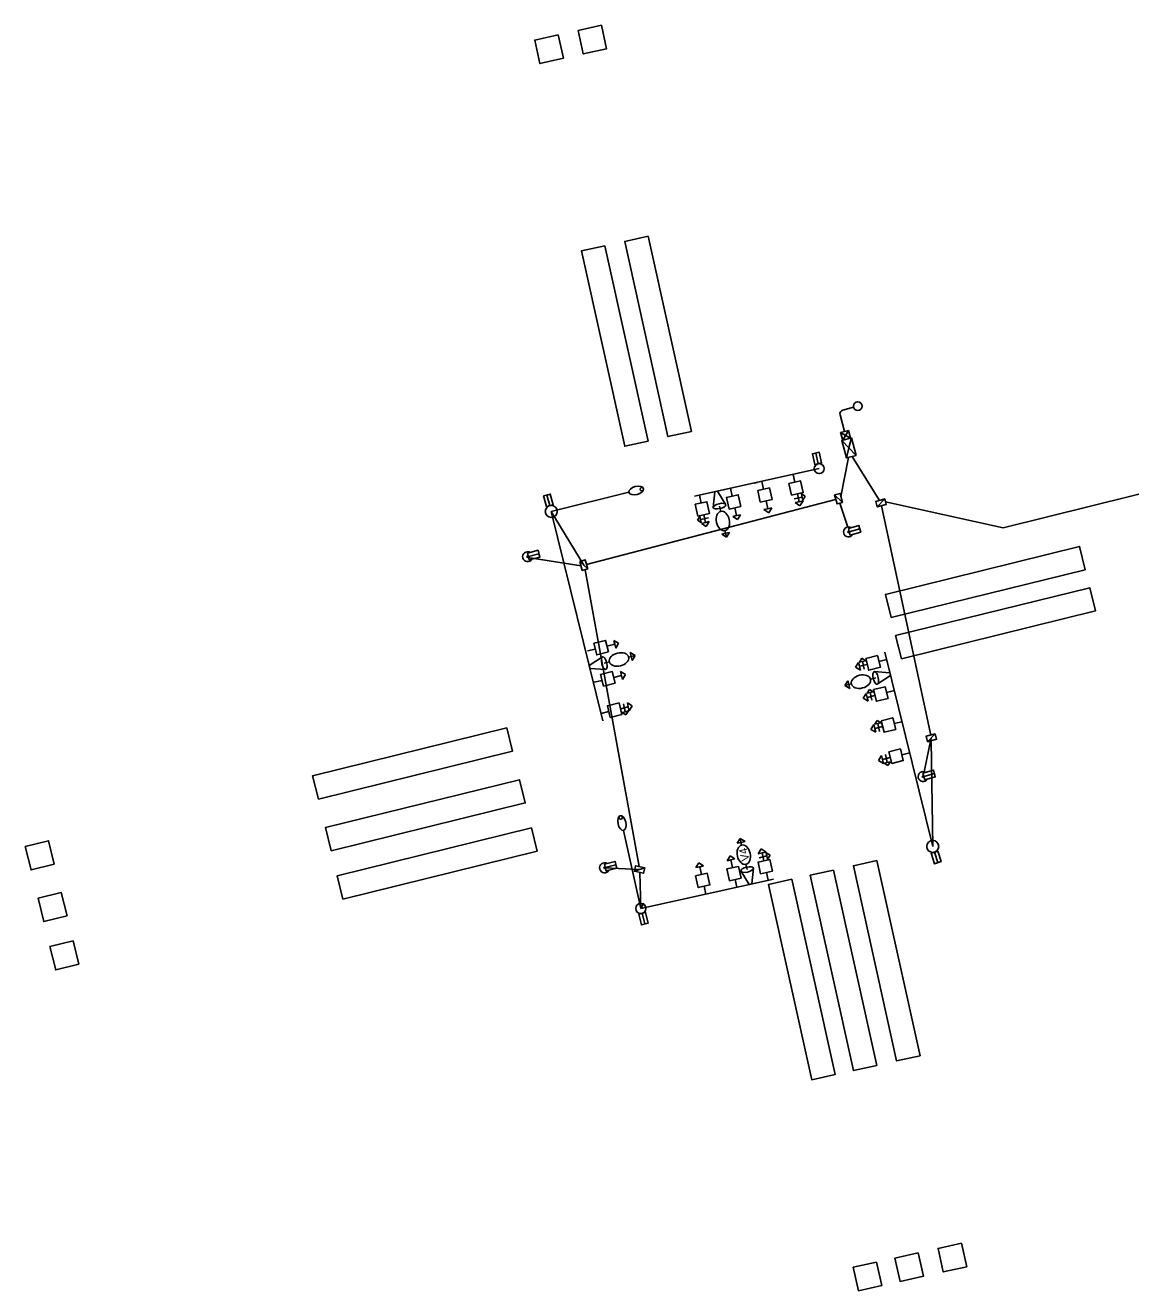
# Model space of a CAD drawing. Extents: x 647787 to 668496, y 640478 to 654412.
# Drawn here: x 666247.6 to 666524.1, y 641782.8 to 642099.1 of the extents above; entities that cross this region are included whole.
import ezdxf

# ---------------------------------------------------------------- set-up
doc = ezdxf.new("R2010")
doc.units = 0
for name, color, linetype in [('Default', 7, 'Continuous'), ('TEMP_DETECTION_ZONE_STAGE 5', 7, 'Continuous'), ('TEMP_SIGNAL_POLES_STAGE 5', 7, 'Continuous')]:
    doc.layers.add(name, color=color, linetype=linetype)

# ---------------------------------------------------------------- blocks, each defined once
blk = doc.blocks.new('pedhead')
at = {"layer": 'TEMP_DETECTION_ZONE_STAGE 5'}
for p, q in [((-2.75, 0.875), (0, 0.875)), ((-2.75, 0), (-2.75, 0.875)), ((-2.75, 0), (0, 0)), ((0, 0), (-2.75, 0)), ((0, 0.875), (0, 0))]:
    blk.add_line(p, q, dxfattribs=at)
for points in [[(0, -0.875), (0, 0.875), (-2.75, 0.875), (-2.75, -0.875)], [(-2.75, 0.875), (0, 0.875), (0, 0), (-2.75, 0)]]:
    blk.add_lwpolyline(points, close=True, dxfattribs=at)
blk = doc.blocks.new('signalcontroller')
at = {"layer": 'TEMP_DETECTION_ZONE_STAGE 5'}
for p, q in [((4.5, 1.25), (0, -1.25)), ((0, 1.25), (4.5, -1.25)), ((0, 1.25), (2.25, 0)), ((4.5, 1.25), (0, 1.25)), ((0, -1.25), (2.25, 0)), ((2.25, 0), (4.5, 1.25)), ((2.25, 0), (4.5, -1.25)), ((6.5, 1), (4.5, -1)), ((4.5, 1), (6.5, -1)), ((4.5, 1), (5.5, 0)), ((6.5, 1), (4.5, 1)), ((4.5, -1), (5.5, 0)), ((5.5, 0), (6.5, 1)), ((5.5, 0), (6.5, -1)), ((4.5, -1.25), (0, -1.25)), ((6.5, -1), (4.5, -1))]:
    blk.add_line(p, q, dxfattribs=at)
for points in [[(0, -1.25), (4.5, -1.25), (4.5, 1.25), (0, 1.25)], [(4.5, -1), (6.5, -1), (6.5, 1), (4.5, 1)]]:
    blk.add_lwpolyline(points, close=True, dxfattribs=at)
for points in [[(0, 1.25), (2.25, 0), (4.5, 1.25), (0, 1.25)], [(0, -1.25), (2.25, 0), (4.5, -1.25), (0, -1.25)], [(4.5, 1), (5.5, 0), (6.5, 1), (4.5, 1)], [(4.5, -1), (5.5, 0), (6.5, -1), (4.5, -1)]]:
    blk.add_lwpolyline(points, dxfattribs=at)
blk = doc.blocks.new('pullbox-type1')
at = {"layer": 'TEMP_DETECTION_ZONE_STAGE 5'}
for p, q in [((1.17, 0.71), (-1.17, -0.71)), ((1.17, -0.71), (1.17, 0.71)), ((-1.17, -0.71), (1.17, -0.71))]:
    blk.add_line(p, q, dxfattribs=at)
blk.add_lwpolyline([(1.17, -0.71), (1.17, 0.71), (-1.17, 0.71), (-1.17, -0.71)], close=True, dxfattribs=at)
blk.add_lwpolyline([(1.17, 0.71), (-1.17, -0.71), (1.17, -0.71), (1.17, 0.71)], dxfattribs=at)
blk = doc.blocks.new('videodetector')
at = {"layer": 'TEMP_DETECTION_ZONE_STAGE 5'}
for p, q in [((3.76, 0.05), (5.11, 0.05)), ((10.04, 0.05), (11.71, 0.05)), ((10.7, 0.05), (10.7, 1.05)), ((10.7, 1.05), (11.71, 0.05)), ((10.7, 0.05), (10.7, 1.05)), ((11.71, 0.05), (10.7, 1.05)), ((11.71, 0.05), (10.7, -0.96)), ((10.7, -0.96), (10.7, 0.05)), ((10.7, 0.05), (10.7, -0.96)), ((11.71, 0.05), (10.7, -0.96))]:
    blk.add_line(p, q, dxfattribs=at)
for points in [[(3.76, 1.68), (0, 0.37)], [(0, 0.37), (0, -0.37)], [(0, -0.37), (3.76, -1.58)]]:
    blk.add_lwpolyline(points, dxfattribs=at)
for centre, major_axis, ratio in [((3.76, 0.05), (0, 1.63), 0.386132), ((7.57, 0.05), (-2.47, 0), 0.662922)]:
    blk.add_ellipse(centre, major_axis=major_axis, ratio=ratio, dxfattribs=at)
blk.add_text('V4', height=2, dxfattribs=at).set_placement((5.93, -1.02))

msp = doc.modelspace()

# ---------------------------------------------------------------- linework, layer by layer
at = {"layer": 'Default'}
msp.add_lwpolyline([(666451.31, 641979.63), (666453.3, 641973.66)], dxfattribs=at)
at = {"layer": 'TEMP_DETECTION_ZONE_STAGE 5'}
for p, q in [((666440.05, 641984.85), (666439.62, 641986.8)), ((666440.05, 641984.85), (666439.62, 641986.8)), ((666424.43, 641981.39), (666424, 641983.34)), ((666424.43, 641981.39), (666424, 641983.34)), ((666432.24, 641983.12), (666431.81, 641985.07)), ((666432.25, 641983.1), (666431.81, 641985.06)), ((666432.25, 641983.1), (666431.81, 641985.06)), ((666416.62, 641979.66), (666416.19, 641981.61)), ((666433.33, 641978.22), (666432.9, 641980.17)), ((666441.9, 641981.16), (666439.94, 641980.73)), ((666441.14, 641979.97), (666440.15, 641979.75)), ((666440.15, 641979.75), (666441.14, 641979.97)), ((666441.35, 641978.99), (666440.15, 641979.75)), ((666441.35, 641978.99), (666440.15, 641979.75)), ((666441.14, 641979.97), (666440.7, 641981.92)), ((666441.14, 641979.97), (666442.12, 641980.19)), ((666441.14, 641979.97), (666442.12, 641980.19)), ((666441.35, 641978.99), (666442.12, 641980.19)), ((666442.12, 641980.19), (666441.35, 641978.99)), ((666441.9, 641981.16), (666441.72, 641981.95)), ((666442.68, 641981.34), (666441.72, 641981.95)), ((666441.9, 641981.16), (666441.72, 641981.95)), ((666441.72, 641981.95), (666442.68, 641981.34)), ((666441.9, 641981.16), (666442.07, 641980.38)), ((666442.07, 641980.38), (666441.9, 641981.16)), ((666442.68, 641981.34), (666442.07, 641980.38)), ((666442.68, 641981.34), (666442.07, 641980.38)), ((666415.73, 641975.37), (666416.34, 641976.32)), ((666415.73, 641975.37), (666416.34, 641976.32)), ((666416.51, 641975.54), (666416.34, 641976.32)), ((666416.34, 641976.32), (666416.51, 641975.54)), ((666417.7, 641974.78), (666417.27, 641976.73)), ((666421.25, 641978.88), (666421.54, 641977.57)), ((666425.51, 641976.51), (666424.53, 641976.29)), ((666424.53, 641976.29), (666425.51, 641976.51)), ((666425.73, 641975.53), (666424.53, 641976.29)), ((666425.73, 641975.53), (666424.53, 641976.29)), ((666425.51, 641976.51), (666425.08, 641978.46)), ((666425.51, 641976.51), (666426.49, 641976.73)), ((666425.51, 641976.51), (666426.49, 641976.73)), ((666425.73, 641975.53), (666426.49, 641976.73)), ((666426.49, 641976.73), (666425.73, 641975.53)), ((666433.33, 641978.22), (666432.35, 641978)), ((666432.35, 641978), (666433.33, 641978.22)), ((666433.55, 641977.24), (666432.35, 641978)), ((666433.55, 641977.24), (666432.35, 641978)), ((666433.33, 641978.22), (666434.31, 641978.44)), ((666433.33, 641978.22), (666434.31, 641978.44)), ((666433.55, 641977.24), (666434.31, 641978.44)), ((666434.31, 641978.44), (666433.55, 641977.24)), ((666415.73, 641975.37), (666416.68, 641974.75)), ((666416.68, 641974.75), (666415.73, 641975.37)), ((666416.51, 641975.54), (666418.46, 641975.97)), ((666416.51, 641975.54), (666416.68, 641974.75)), ((666416.51, 641975.54), (666416.68, 641974.75)), ((666417.7, 641974.78), (666416.72, 641974.56)), ((666416.72, 641974.56), (666417.7, 641974.78)), ((666417.92, 641973.8), (666416.72, 641974.56)), ((666417.92, 641973.8), (666416.72, 641974.56)), ((666417.7, 641974.78), (666418.68, 641975)), ((666417.7, 641974.78), (666418.68, 641975)), ((666417.92, 641973.8), (666418.68, 641975)), ((666418.68, 641975), (666417.92, 641973.8)), ((666422.75, 641972.1), (666421.77, 641971.89)), ((666421.77, 641971.89), (666422.75, 641972.1)), ((666422.96, 641971.12), (666421.77, 641971.89)), ((666422.96, 641971.12), (666421.77, 641971.89)), ((666422.6, 641972.75), (666422.96, 641971.12)), ((666422.75, 641972.1), (666423.73, 641972.32)), ((666422.75, 641972.1), (666423.73, 641972.32)), ((666422.96, 641971.12), (666423.73, 641972.32)), ((666423.73, 641972.32), (666422.96, 641971.12)), ((666395.02, 641944.35), (666394.78, 641945.33)), ((666395.99, 641944.59), (666394.78, 641945.33)), ((666395.02, 641944.35), (666394.78, 641945.33)), ((666394.78, 641945.33), (666395.99, 641944.59)), ((666395.99, 641944.59), (666395.26, 641943.38)), ((666395.99, 641944.59), (666395.26, 641943.38)), ((666390.16, 641943.15), (666388.22, 641942.68)), ((666395.02, 641944.35), (666393.08, 641943.87)), ((666395.02, 641944.35), (666395.26, 641943.38)), ((666395.26, 641943.38), (666395.02, 641944.35)), ((666398.48, 641941.14), (666400.1, 641941.54)), ((666399.12, 641941.3), (666398.88, 641942.28)), ((666400.1, 641941.54), (666398.88, 641942.28)), ((666399.12, 641941.3), (666398.88, 641942.28)), ((666398.88, 641942.28), (666400.1, 641941.54)), ((666400.1, 641941.54), (666399.36, 641940.33)), ((666400.1, 641941.54), (666399.36, 641940.33)), ((666392.39, 641939.64), (666393.69, 641939.96)), ((666399.12, 641941.3), (666399.36, 641940.33)), ((666399.36, 641940.33), (666399.12, 641941.3)), ((666455.27, 641938.61), (666456, 641939.82)), ((666455.27, 641938.61), (666456, 641939.82)), ((666455.27, 641938.61), (666456.48, 641937.87)), ((666456.48, 641937.87), (666455.27, 641938.61)), ((666456.24, 641938.85), (666456, 641939.82)), ((666456, 641939.82), (666456.24, 641938.85)), ((666456.83, 641940.85), (666456.21, 641939.89)), ((666456.21, 641939.89), (666456.83, 641940.85)), ((666457, 641940.06), (666456.21, 641939.89)), ((666457, 641940.06), (666456.21, 641939.89)), ((666456.24, 641938.85), (666458.19, 641939.33)), ((666456.24, 641938.85), (666456.48, 641937.87)), ((666456.24, 641938.85), (666456.48, 641937.87)), ((666456.83, 641940.85), (666457.78, 641940.24)), ((666456.83, 641940.85), (666457.78, 641940.24)), ((666457, 641940.06), (666457.78, 641940.24)), ((666457.78, 641940.24), (666457, 641940.06)), ((666457, 641940.06), (666457.43, 641938.11)), ((666461.1, 641940.04), (666463.04, 641940.52)), ((666391.86, 641935.33), (666389.92, 641934.85)), ((666396.72, 641936.53), (666394.78, 641936.05)), ((666396.72, 641936.53), (666396.48, 641937.51)), ((666397.69, 641936.77), (666396.48, 641937.51)), ((666396.72, 641936.53), (666396.48, 641937.51)), ((666396.48, 641937.51), (666397.69, 641936.77)), ((666396.72, 641936.53), (666396.96, 641935.55)), ((666396.96, 641935.55), (666396.72, 641936.53)), ((666397.69, 641936.77), (666396.96, 641935.55)), ((666397.69, 641936.77), (666396.96, 641935.55)), ((666452.59, 641934.02), (666453.32, 641935.24)), ((666452.59, 641934.02), (666453.32, 641935.24)), ((666453.56, 641934.26), (666453.32, 641935.24)), ((666453.32, 641935.24), (666453.56, 641934.26)), ((666460.3, 641935.92), (666458.99, 641935.6)), ((666454.2, 641934.42), (666452.59, 641934.02)), ((666452.59, 641934.02), (666453.8, 641933.29)), ((666453.8, 641933.29), (666452.59, 641934.02)), ((666453.56, 641934.26), (666453.8, 641933.29)), ((666453.56, 641934.26), (666453.8, 641933.29)), ((666457.18, 641930.84), (666457.92, 641932.06)), ((666457.18, 641930.84), (666457.92, 641932.06)), ((666458.16, 641931.08), (666457.92, 641932.06)), ((666457.92, 641932.06), (666458.16, 641931.08)), ((666458.74, 641933.08), (666458.13, 641932.12)), ((666458.13, 641932.12), (666458.74, 641933.08)), ((666458.91, 641932.3), (666458.13, 641932.12)), ((666458.91, 641932.3), (666458.13, 641932.12)), ((666458.74, 641933.08), (666459.7, 641932.47)), ((666458.74, 641933.08), (666459.7, 641932.47)), ((666458.91, 641932.3), (666459.7, 641932.47)), ((666459.7, 641932.47), (666458.91, 641932.3)), ((666458.91, 641932.3), (666459.35, 641930.34)), ((666463.01, 641932.28), (666464.96, 641932.76)), ((666463.01, 641932.28), (666464.96, 641932.76)), ((666398.42, 641928.71), (666396.47, 641928.23)), ((666397.66, 641927.49), (666397.23, 641929.45)), ((666398.42, 641928.71), (666398.18, 641929.69)), ((666399.39, 641928.95), (666398.18, 641929.69)), ((666398.42, 641928.71), (666398.18, 641929.69)), ((666398.18, 641929.69), (666399.39, 641928.95)), ((666398.42, 641928.71), (666398.66, 641927.73)), ((666398.66, 641927.73), (666398.42, 641928.71)), ((666399.39, 641928.95), (666398.66, 641927.73)), ((666399.39, 641928.95), (666398.66, 641927.73)), ((666457.18, 641930.84), (666458.4, 641930.11)), ((666458.4, 641930.11), (666457.18, 641930.84)), ((666458.16, 641931.08), (666460.1, 641931.56)), ((666458.16, 641931.08), (666458.4, 641930.11)), ((666458.16, 641931.08), (666458.4, 641930.11)), ((666393.56, 641927.51), (666391.62, 641927.03)), ((666397.66, 641927.49), (666396.88, 641927.32)), ((666396.88, 641927.32), (666397.66, 641927.49)), ((666397.84, 641926.71), (666396.88, 641927.32)), ((666397.84, 641926.71), (666396.88, 641927.32)), ((666397.66, 641927.49), (666398.45, 641927.67)), ((666397.66, 641927.49), (666398.45, 641927.67)), ((666397.84, 641926.71), (666398.45, 641927.67)), ((666398.45, 641927.67), (666397.84, 641926.71)), ((666459.1, 641923.07), (666459.83, 641924.29)), ((666459.1, 641923.07), (666459.83, 641924.29)), ((666459.1, 641923.07), (666460.32, 641922.34)), ((666460.32, 641922.34), (666459.1, 641923.07)), ((666460.07, 641923.31), (666459.83, 641924.29)), ((666459.83, 641924.29), (666460.07, 641923.31)), ((666460.66, 641925.31), (666460.04, 641924.36)), ((666460.04, 641924.36), (666460.66, 641925.31)), ((666460.83, 641924.53), (666460.04, 641924.36)), ((666460.83, 641924.53), (666460.04, 641924.36)), ((666460.07, 641923.31), (666462.02, 641923.79)), ((666460.07, 641923.31), (666460.32, 641922.34)), ((666460.07, 641923.31), (666460.32, 641922.34)), ((666460.66, 641925.31), (666461.61, 641924.7)), ((666460.66, 641925.31), (666461.61, 641924.7)), ((666460.83, 641924.53), (666461.61, 641924.7)), ((666461.61, 641924.7), (666460.83, 641924.53)), ((666460.83, 641924.53), (666461.26, 641922.58)), ((666464.93, 641924.51), (666466.87, 641924.99)), ((666464.93, 641924.51), (666466.87, 641924.99)), ((666461.01, 641915.31), (666461.75, 641916.52)), ((666461.01, 641915.31), (666461.75, 641916.52)), ((666461.99, 641915.55), (666461.75, 641916.52)), ((666461.75, 641916.52), (666461.99, 641915.55)), ((666461.99, 641915.55), (666463.93, 641916.02)), ((666463.18, 641914.81), (666462.74, 641916.76)), ((666466.84, 641916.74), (666468.79, 641917.22)), ((666466.84, 641916.74), (666468.79, 641917.22)), ((666461.01, 641915.31), (666462.23, 641914.57)), ((666462.23, 641914.57), (666461.01, 641915.31)), ((666461.99, 641915.55), (666462.23, 641914.57)), ((666461.99, 641915.55), (666462.23, 641914.57)), ((666463.18, 641914.81), (666462.39, 641914.64)), ((666462.39, 641914.64), (666463.18, 641914.81)), ((666463.35, 641914.02), (666462.39, 641914.64)), ((666463.35, 641914.02), (666462.39, 641914.64)), ((666463.18, 641914.81), (666463.96, 641914.98)), ((666463.18, 641914.81), (666463.96, 641914.98)), ((666463.35, 641914.02), (666463.96, 641914.98)), ((666463.96, 641914.98), (666463.35, 641914.02)), ((666423.87, 641891.44), (666423.11, 641890.24)), ((666423.11, 641890.24), (666423.87, 641891.44)), ((666423.87, 641891.44), (666425.07, 641890.68)), ((666423.87, 641891.44), (666425.07, 641890.68)), ((666431.68, 641893.17), (666430.92, 641891.97)), ((666430.92, 641891.97), (666431.68, 641893.17)), ((666431.9, 641892.19), (666430.92, 641891.97)), ((666431.9, 641892.19), (666430.92, 641891.97)), ((666433.09, 641891.43), (666431.14, 641891)), ((666431.68, 641893.17), (666432.88, 641892.41)), ((666431.68, 641893.17), (666432.88, 641892.41)), ((666431.9, 641892.19), (666432.88, 641892.41)), ((666432.88, 641892.41), (666431.9, 641892.19)), ((666431.9, 641892.19), (666432.33, 641890.24)), ((666433.09, 641891.43), (666432.92, 641892.21)), ((666433.88, 641891.6), (666432.92, 641892.21)), ((666433.09, 641891.43), (666432.92, 641892.21)), ((666432.92, 641892.21), (666433.88, 641891.6)), ((666433.09, 641891.43), (666433.27, 641890.64)), ((666433.27, 641890.64), (666433.09, 641891.43)), ((666433.88, 641891.6), (666433.27, 641890.64)), ((666433.88, 641891.6), (666433.27, 641890.64)), ((666416.06, 641889.71), (666415.3, 641888.51)), ((666415.3, 641888.51), (666416.06, 641889.71)), ((666416.28, 641888.73), (666415.3, 641888.51)), ((666416.28, 641888.73), (666415.3, 641888.51)), ((666416.06, 641889.71), (666417.26, 641888.95)), ((666416.06, 641889.71), (666417.26, 641888.95)), ((666416.28, 641888.73), (666417.26, 641888.95)), ((666417.26, 641888.95), (666416.28, 641888.73)), ((666416.28, 641888.73), (666416.71, 641886.78)), ((666424.09, 641890.46), (666423.11, 641890.24)), ((666424.09, 641890.46), (666423.11, 641890.24)), ((666424.09, 641890.46), (666425.07, 641890.68)), ((666425.07, 641890.68), (666424.09, 641890.46)), ((666424.09, 641890.46), (666424.52, 641888.51)), ((666425.17, 641885.58), (666425.6, 641883.62)), ((666432.98, 641887.31), (666433.41, 641885.35)), ((666417.36, 641883.85), (666417.79, 641881.89)), ((666402.31, 641879.6), (666401.56, 641878.3))]:
    msp.add_line(p, q, dxfattribs=at)
for points in [[(666462.75, 641979.99), (666492.21, 641973.49), (666665.6, 642016.47), (666782.14, 642043.1), (666870.44, 642058.1), (666911.78, 642069.17)], [(666451.38, 642001.67), (666452.49, 641997.53)], [(666454.75, 642003.61), (666452.09, 642002.89)], [(666453.49, 641991.07), (666451.59, 641981.29)], [(666454.41, 641991.31), (666461.23, 641980.32)], [(666446.18, 641988.26), (666414.94, 641981.34)], [(666420.02, 641982.46), (666419.66, 641978.53)], [(666422.84, 641979.23), (666420.75, 641982.62)], [(666422.93, 641983.11), (666422.2, 641982.95)], [(666430.75, 641984.82), (666430.02, 641984.66)], [(666379.16, 641977.55), (666398.58, 641982.34)], [(666450.2, 641980.53), (666387.97, 641964.3)], [(666379.16, 641977.55), (666392.06, 641925.24)], [(666387.29, 641964.12), (666379.16, 641977.55)], [(666461.77, 641978.99), (666474.05, 641921.66)], [(666386.6, 641963.93), (666373.29, 641966.06)], [(666387.59, 641962.99), (666401.11, 641888.8)], [(666474.56, 641893.81), (666462.59, 641942.36)], [(666392, 641941.22), (666388.66, 641939.06)], [(666388.66, 641939.06), (666388.83, 641938.33)], [(666388.83, 641938.33), (666392.78, 641938.06)], [(666463.85, 641937.23), (666459.91, 641937.5)], [(666460.69, 641934.34), (666464.03, 641936.51)], [(666464.03, 641936.51), (666463.85, 641937.23)], [(666474.2, 641920.97), (666472.4, 641912.5)], [(666474.16, 641920.22), (666474.56, 641893.81)], [(666401.56, 641878.3), (666397.23, 641897.82)], [(666401.25, 641888.04), (666392.49, 641888.47)], [(666401.27, 641887.31), (666401.56, 641878.3)], [(666401.56, 641878.3), (666434.75, 641885.65)]]:
    msp.add_lwpolyline(points, dxfattribs=at)
for points in [[(666431.43, 641979.85), (666434.36, 641980.5), (666433.71, 641983.43), (666430.78, 641982.78)], [(666439.24, 641981.6), (666442.17, 641982.25), (666441.52, 641985.18), (666438.59, 641984.53)], [(666415.81, 641976.41), (666418.74, 641977.06), (666418.09, 641979.99), (666415.16, 641979.34)], [(666423.62, 641978.14), (666426.55, 641978.79), (666425.9, 641981.72), (666422.97, 641981.07)], [(666393.44, 641942.42), (666392.72, 641945.33), (666389.8, 641944.61), (666390.52, 641941.7)], [(666457.83, 641940.78), (666458.55, 641937.87), (666461.46, 641938.59), (666460.74, 641941.5)], [(666395.13, 641934.6), (666394.42, 641937.51), (666391.5, 641936.79), (666392.22, 641933.88)], [(666459.74, 641933.02), (666460.46, 641930.1), (666463.37, 641930.82), (666462.66, 641933.73)], [(666396.83, 641926.77), (666396.12, 641929.69), (666393.2, 641928.97), (666393.92, 641926.06)], [(666461.66, 641925.25), (666462.38, 641922.34), (666465.29, 641923.05), (666464.57, 641925.97)], [(666463.57, 641917.48), (666464.29, 641914.57), (666467.2, 641915.29), (666466.49, 641918.2)], [(666425.99, 641888.83), (666423.06, 641888.18), (666423.71, 641885.25), (666426.63, 641885.9)], [(666433.8, 641890.56), (666430.87, 641889.91), (666431.52, 641886.98), (666434.45, 641887.63)], [(666418.18, 641887.1), (666415.25, 641886.45), (666415.9, 641883.52), (666418.82, 641884.17)]]:
    msp.add_lwpolyline(points, close=True, dxfattribs=at)
for centre, radius in [((666455.79, 642003.89), 1.08), ((666446.18, 641988.26), 1.25), ((666446.18, 641988.26), 1.25), ((666401.8, 641983.13), 0.441), ((666379.16, 641977.55), 1.5), ((666379.16, 641977.55), 1.5), ((666453.5, 641972.43), 0.188), ((666453.5, 641972.43), 0.187), ((666373.24, 641966.24), 0.188), ((666373.24, 641966.24), 0.187), ((666472.14, 641911.28), 0.188), ((666472.14, 641911.28), 0.187), ((666396.52, 641901.05), 0.441), ((666474.56, 641893.81), 1.5), ((666474.56, 641893.81), 1.5), ((666392.49, 641888.47), 0.188), ((666392.49, 641888.47), 0.187), ((666401.56, 641878.3), 1.25), ((666401.56, 641878.3), 1.25)]:
    msp.add_circle(centre, radius, dxfattribs=at)
for centre, radius, start, end in [((666452.35, 642001.93), 1, 105, 195), ((666453.5, 641972.43), 1.25, 59.427, 330.573), ((666373.24, 641966.24), 1.25, 59.427, 330.573), ((666472.14, 641911.28), 1.25, 59.427, 330.573), ((666392.49, 641888.47), 1.25, 59.427, 330.573)]:
    msp.add_arc(centre, radius, start, end, dxfattribs=at)
for centre, major_axis, ratio in [((666400.4, 641982.79), (1.82, 0.45), 0.533333), ((666421.25, 641978.88), (1.59, 0.35), 0.386132), ((666422.07, 641975.16), (-0.53, 2.41), 0.662922), ((666396.09, 641940.55), (-2.4, -0.59), 0.662922), ((666392.39, 641939.64), (-0.39, 1.58), 0.386132), ((666456.6, 641935.01), (2.4, 0.59), 0.662922), ((666460.3, 641935.92), (0.39, -1.58), 0.386132), ((666396.83, 641899.66), (-0.41, 1.83), 0.533333)]:
    msp.add_ellipse(centre, major_axis=major_axis, ratio=ratio, dxfattribs=at)
at = {"layer": 'TEMP_SIGNAL_POLES_STAGE 5'}
for points in [[(666380.89, 642096.69), (666375.03, 642095.39), (666376.33, 642089.53), (666382.18, 642090.83)], [(666391.71, 642099.08), (666385.85, 642097.78), (666387.15, 642091.93), (666393, 642093.22)], [(666403.38, 642046.36), (666397.53, 642045.06), (666408.34, 641996.25), (666414.2, 641997.54)], [(666392.56, 642043.96), (666386.71, 642042.67), (666397.52, 641993.85), (666403.38, 641995.15)], [(666464.17, 641951.01), (666512.72, 641962.98), (666511.28, 641968.8), (666462.74, 641956.83)], [(666466.71, 641940.7), (666515.26, 641952.67), (666513.82, 641958.49), (666465.28, 641946.52)], [(666320.9, 641905.66), (666319.46, 641911.49), (666368.01, 641923.45), (666369.45, 641917.62)], [(666324.09, 641892.71), (666322.65, 641898.54), (666371.2, 641910.5), (666372.64, 641904.67)], [(666327.06, 641880.65), (666325.62, 641886.48), (666374.17, 641898.45), (666375.61, 641892.62)], [(666254.87, 641889.39), (666253.44, 641895.22), (666247.61, 641893.78), (666249.05, 641887.95)], [(666449.75, 641887.89), (666443.89, 641886.6), (666454.7, 641837.78), (666460.56, 641839.08)], [(666460.57, 641890.29), (666454.71, 641888.99), (666465.53, 641840.18), (666471.38, 641841.47)], [(666439.34, 641885.59), (666433.48, 641884.29), (666444.29, 641835.47), (666450.15, 641836.77)], [(666258.06, 641876.46), (666256.62, 641882.29), (666250.8, 641880.85), (666252.23, 641875.02)], [(666261.04, 641864.37), (666259.6, 641870.2), (666253.78, 641868.76), (666255.21, 641862.93)], [(666481.76, 641794.61), (666475.91, 641793.31), (666477.2, 641787.45), (666483.06, 641788.75)], [(666460.53, 641789.91), (666454.67, 641788.61), (666455.97, 641782.75), (666461.83, 641784.05)], [(666470.94, 641792.21), (666465.08, 641790.92), (666466.38, 641785.06), (666472.24, 641786.35)]]:
    msp.add_lwpolyline(points, close=True, dxfattribs=at)

# ---------------------------------------------------------------- block references
at = {"layer": 'Default', "rotation": 102.488966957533}
msp.add_blockref('videodetector', (666428.99, 641884.37), dxfattribs=at)
at = {"layer": 'TEMP_DETECTION_ZONE_STAGE 5'}
for name, p, rotation in [('signalcontroller', (666454.17, 641991.25), 104.99999999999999), ('pedhead', (666445.32, 641992.16), 102.48899999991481), ('pedhead', (666378.78, 641979), -75.00000000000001), ('pullbox-type1', (666451, 641980.75), 104.99999999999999), ('pullbox-type1', (666461.63, 641979.69), 14.999999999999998), ('pedhead', (666453.68, 641972.48), -165.00000000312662), ('pedhead', (666373.42, 641966.28), -165.00000000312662), ('pullbox-type1', (666387.29, 641964.12), -75.00000000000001), ('pullbox-type1', (666474.2, 641920.97), 14.999999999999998), ('pedhead', (666472.32, 641911.32), -165.00000000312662), ('pedhead', (666475, 641892.38), 107.3479999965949), ('pedhead', (666392.67, 641888.52), -165.00000000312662), ('pullbox-type1', (666401.25, 641888.04), 167.8383875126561)]:
    msp.add_blockref(name, p, dxfattribs=dict(at, rotation=rotation))
at = {"layer": 'TEMP_DETECTION_ZONE_STAGE 5', "yscale": -0.9999999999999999, "rotation": 103.85049999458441}
msp.add_blockref('pedhead', (666401.88, 641877.09), dxfattribs=at)

doc.saveas('drawing.dxf')
